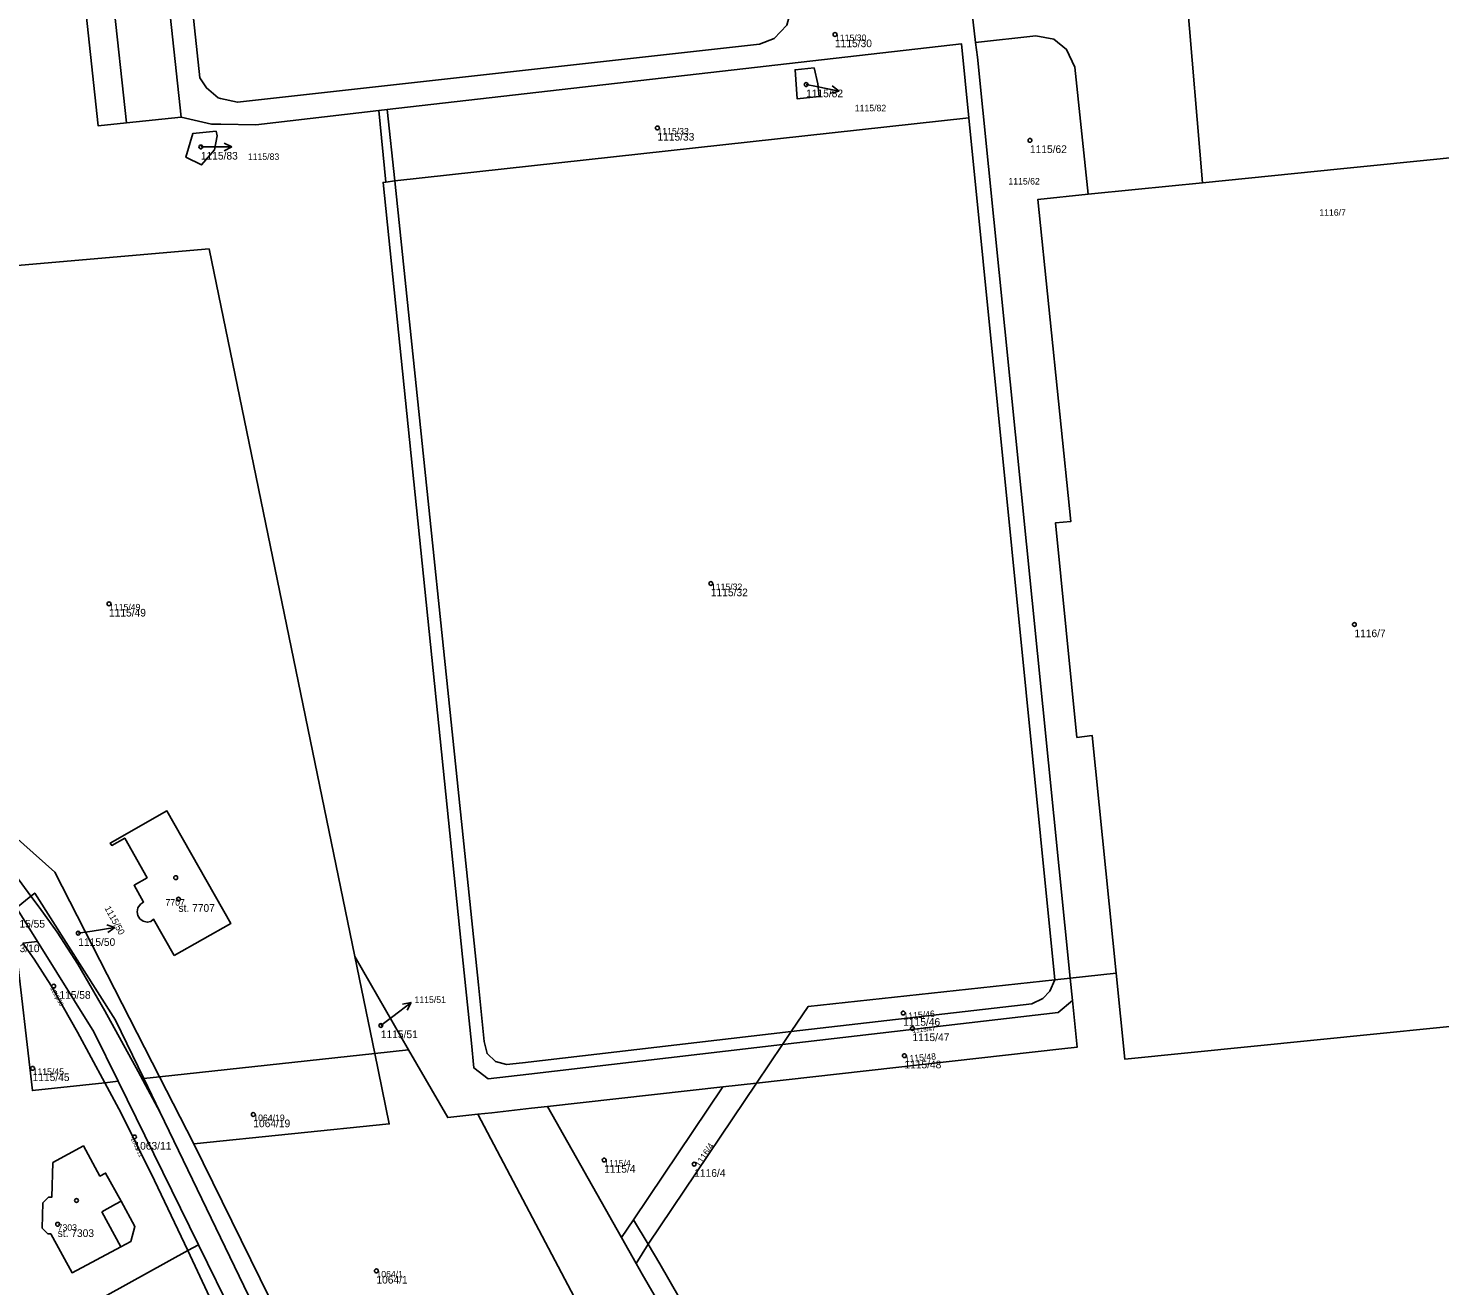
# Model space of a CAD drawing. Extents: x -543948 to -537130, y -1157612 to -1152122.
# Drawn here: x -539604.9 to -539420.2, y -1156400.3 to -1156235.7 of the extents above; entities that cross this region are included whole.
import ezdxf

# ---------------------------------------------------------------- set-up
doc = ezdxf.new("R2010")
doc.units = 0
for name, color, linetype in [('Definiční body', 7, 'Continuous'), ('Hranice parcel', 7, 'Continuous'), ('Parcelní čísla', 7, 'Continuous'), ('Pop  PČ popisy', 7, 'Continuous'), ('Vnitřní kresba', 7, 'Continuous')]:
    doc.layers.add(name, color=color, linetype=linetype)

msp = doc.modelspace()

# ---------------------------------------------------------------- linework, layer by layer
at = {"layer": 'Definiční body'}
for centre in [(-539499.3, -1156236.52994), (-539503.08, -1156243.07994), (-539522.54, -1156248.75994), (-539582.28, -1156251.23994), (-539473.79, -1156250.37994), (-539515.54, -1156308.37994), (-539594.3, -1156311.03994), (-539431.33, -1156313.73994), (-539585.57, -1156346.86994), (-539585.21, -1156349.67994), (-539598.32, -1156354.13994), (-539601.54, -1156361.05994), (-539490.37, -1156364.58994), (-539558.73, -1156366.20994), (-539489.17, -1156366.59994), (-539490.22, -1156370.16994), (-539604.3, -1156371.82994), (-539575.42, -1156377.86994), (-539590.97, -1156380.79994), (-539529.5, -1156383.81994), (-539517.72, -1156384.35994), (-539598.55, -1156389.10994), (-539601.02, -1156392.22994), (-539559.31, -1156398.32994)]:
    msp.add_circle(centre, 0.25, dxfattribs=at)
at = {"layer": 'Hranice parcel'}
for p, q in [((-539595.49, -1156215.97), (-539592.02, -1156248.1)), ((-539451.22, -1156255.93), (-539453.41, -1156229.63)), ((-539481.48, -1156232.65), (-539480.91, -1156237.57)), ((-539592.02, -1156248.1), (-539584.86, -1156247.33)), ((-539481.78, -1156247.42), (-539556.9, -1156255.68)), ((-539481.78, -1156247.42), (-539470.52, -1156360.23)), ((-539607.73, -1156344.92), (-539604.51, -1156349.29)), ((-539605.57, -1156355.43), (-539603.66, -1156355.21)), ((-539562.13, -1156357.18), (-539555.09, -1156369.4)), ((-539559.52, -1156369.88), (-539562.13, -1156357.18)), ((-539470.52, -1156360.23), (-539468.52, -1156360.01)), ((-539462.52, -1156359.36), (-539468.52, -1156360.01)), ((-539468.23, -1156362.94), (-539468.52, -1156360.01)), ((-539506.18, -1156368.72), (-539505.04, -1156367.02)), ((-539555.09, -1156369.4), (-539559.52, -1156369.88)), ((-539509.56, -1156373.75), (-539506.18, -1156368.72)), ((-539559.52, -1156369.88), (-539587.7, -1156372.94)), ((-539587.7, -1156372.94), (-539589.75, -1156373.16)), ((-539593.11, -1156373.52), (-539594.84, -1156373.71)), ((-539593.11, -1156373.52), (-539582.6, -1156394.91)), ((-539513.96, -1156374.24), (-539536.94, -1156376.82)), ((-539525.68, -1156391.66), (-539513.96, -1156374.24)), ((-539509.56, -1156373.75), (-539523.77, -1156394.85)), ((-539513.96, -1156374.24), (-539509.56, -1156373.75)), ((-539536.94, -1156376.82), (-539527.23, -1156393.96)), ((-539527.23, -1156393.96), (-539525.68, -1156391.66)), ((-539525.68, -1156391.66), (-539523.77, -1156394.85)), ((-539582.6, -1156394.91), (-539584, -1156395.68)), ((-539582.6, -1156394.91), (-539573.33, -1156413.75)), ((-539584, -1156395.68), (-539617.21, -1156414.01)), ((-539575.06, -1156414.65), (-539584, -1156395.68))]:
    msp.add_line(p, q, dxfattribs=at)
for points in [[(-539584.86, -1156247.33), (-539597.37, -1156131.17), (-539596.62, -1156128.94), (-539594.87, -1156127.75), (-539561.36, -1156124.05), (-539517.61, -1156119.21)], [(-539509.18, -1156237.78), (-539577.5, -1156245.39), (-539579.7, -1156244.89), (-539580, -1156244.82), (-539581.55, -1156243.51), (-539582.4, -1156242.19), (-539593.77, -1156135.82), (-539593.44, -1156133.31), (-539591.5, -1156131), (-539589.11, -1156130.23), (-539562.35, -1156127.29), (-539521.85, -1156122.83), (-539518.9, -1156124.09), (-539517.15, -1156126.01), (-539515.99, -1156128.84), (-539505.04, -1156233.24), (-539505.6, -1156235.31), (-539507.26, -1156237.06), (-539509.18, -1156237.78)], [(-539592.02, -1156248.1), (-539595.7, -1156248.5), (-539599.16, -1156216.36)], [(-539556.9, -1156255.68), (-539557.91, -1156246.35), (-539482.74, -1156237.75), (-539481.78, -1156247.42)], [(-539480.91, -1156237.57), (-539473.03, -1156236.7), (-539470.68, -1156237.13), (-539469, -1156238.47), (-539467.92, -1156240.79), (-539466.17, -1156257.44)], [(-539468.52, -1156360.01), (-539480.66, -1156239.51), (-539480.91, -1156237.57)], [(-539502.04, -1156240.91), (-539501.54, -1156243), (-539501.36, -1156244.62), (-539504.26, -1156244.93), (-539504.53, -1156241.14), (-539502.04, -1156240.91)], [(-539584.86, -1156247.33), (-539580.91, -1156248.24), (-539579.68, -1156248.26), (-539575.09, -1156248.34), (-539559, -1156246.48), (-539558.07, -1156255.83), (-539558.43, -1156255.88), (-539548.03, -1156357.24), (-539546.87, -1156368.51), (-539546.54, -1156371.77), (-539544.68, -1156373.19), (-539539.35, -1156372.57), (-539506.18, -1156368.72)], [(-539580.27, -1156249.17), (-539580.13, -1156249.78), (-539580.51, -1156251.61), (-539582.18, -1156253.6), (-539584.23, -1156252.6), (-539583.34, -1156249.5), (-539580.27, -1156249.17)], [(-539451.22, -1156255.93), (-539433.13, -1156254.11), (-539428.78, -1156253.67), (-539398.93, -1156250.66), (-539387.62, -1156363.22), (-539461.39, -1156370.62), (-539462.52, -1156359.36)], [(-539505.04, -1156367.02), (-539540.19, -1156371.09), (-539542.29, -1156371.33), (-539543.73, -1156370.93), (-539544.82, -1156369.88), (-539545.19, -1156368.33), (-539545.96, -1156360.89), (-539556.9, -1156255.68)], [(-539466.17, -1156257.44), (-539460.03, -1156256.82), (-539451.22, -1156255.93)], [(-539462.52, -1156359.36), (-539465.63, -1156328.27), (-539467.64, -1156328.52), (-539470.46, -1156300.44), (-539468.45, -1156300.26), (-539472.75, -1156258.1), (-539466.17, -1156257.44)], [(-539613.86, -1156267.42), (-539581.21, -1156264.59), (-539562.13, -1156357.18)], [(-539585.76, -1156357.05), (-539588.46, -1156352.32), (-539588.83, -1156352.61), (-539589.29, -1156352.7), (-539589.83, -1156352.55), (-539590.25, -1156352.25), (-539590.52, -1156351.81), (-539590.6, -1156351.33), (-539590.51, -1156350.81), (-539590.17, -1156350.34), (-539589.78, -1156350.07), (-539591.03, -1156347.85), (-539589.32, -1156346.88), (-539592.24, -1156341.69), (-539593.95, -1156342.65), (-539594.13, -1156342.34), (-539586.73, -1156338.14), (-539578.37, -1156352.87), (-539585.76, -1156357.05)], [(-539608.29, -1156339.98), (-539601.38, -1156346.14), (-539587.7, -1156372.94)], [(-539589.75, -1156373.16), (-539593.45, -1156365.5), (-539604.02, -1156348.89), (-539604.51, -1156349.29)], [(-539604.51, -1156349.29), (-539606.4, -1156350.81), (-539603.66, -1156355.21)], [(-539594.84, -1156373.71), (-539604.33, -1156374.74), (-539606.52, -1156355.54)], [(-539594.84, -1156373.71), (-539598.42, -1156367.07), (-539601.93, -1156360.95), (-539604.08, -1156357.55), (-539605.57, -1156355.43)], [(-539603.66, -1156355.21), (-539596.29, -1156367.06), (-539593.11, -1156373.52)], [(-539505.04, -1156367.02), (-539502.83, -1156363.73), (-539470.52, -1156360.23)], [(-539505.04, -1156367.02), (-539473.55, -1156363.37), (-539472.1, -1156362.68), (-539471.17, -1156361.7), (-539470.52, -1156360.23)], [(-539509.56, -1156373.75), (-539469.61, -1156369.27), (-539467.62, -1156369.05), (-539468.23, -1156362.94)], [(-539506.18, -1156368.72), (-539470.08, -1156364.52), (-539468.23, -1156362.94)], [(-539546.04, -1156377.83), (-539549.98, -1156378.27), (-539555.09, -1156369.4)], [(-539559.52, -1156369.88), (-539557.62, -1156379.09), (-539583.22, -1156381.7), (-539587.7, -1156372.94)], [(-539563.35, -1156427.84), (-539575.44, -1156402.8), (-539587.65, -1156377.51), (-539589.75, -1156373.16)], [(-539584, -1156395.68), (-539588.35, -1156386.52), (-539592.7, -1156377.68), (-539594.84, -1156373.71)], [(-539546.04, -1156377.83), (-539544.22, -1156377.63), (-539539.01, -1156377.05), (-539536.94, -1156376.82)], [(-539523.54, -1156417.22), (-539532.55, -1156403.4), (-539546.04, -1156377.83)], [(-539602.94, -1156389.43), (-539603.03, -1156392.72), (-539602.29, -1156393.49), (-539601.93, -1156393.5), (-539599.14, -1156398.57), (-539592.77, -1156395.17), (-539591.44, -1156394.47), (-539590.92, -1156392.52), (-539592.73, -1156389.21), (-539594.75, -1156385.52), (-539595.48, -1156385.93), (-539597.64, -1156381.98), (-539601.66, -1156384.16), (-539601.8, -1156388.69), (-539602.21, -1156388.68), (-539602.94, -1156389.43)], [(-539434.28, -1156563.31), (-539454.24, -1156517.51), (-539476.7, -1156481.18), (-539524.52, -1156398.74), (-539525.3, -1156397.36), (-539527.23, -1156393.96)], [(-539523.77, -1156394.85), (-539522.23, -1156397.42), (-539474.85, -1156479.9), (-539452.25, -1156516.35), (-539431.27, -1156560.89)]]:
    msp.add_lwpolyline(points, dxfattribs=at)
at = {"layer": 'Pop  PČ popisy'}
for p, q in [((-539503.08, -1156243.08), (-539501.72, -1156243.35)), ((-539501.72, -1156243.35), (-539498.774, -1156243.923)), ((-539498.774, -1156243.923), (-539499.853, -1156244.223)), ((-539498.774, -1156243.923), (-539499.662, -1156243.24)), ((-539581.23, -1156251.24), (-539582.28, -1156251.24)), ((-539581.23, -1156251.24), (-539578.229, -1156251.24)), ((-539578.229, -1156251.24), (-539579.23, -1156250.739)), ((-539578.229, -1156251.24), (-539579.23, -1156251.741)), ((-539598.32, -1156354.14), (-539596.5, -1156353.85)), ((-539596.5, -1156353.85), (-539593.536, -1156353.381)), ((-539593.536, -1156353.381), (-539594.603, -1156353.043)), ((-539593.536, -1156353.381), (-539594.447, -1156354.032)), ((-539557.18, -1156365.02), (-539554.783, -1156363.214)), ((-539554.783, -1156363.214), (-539555.884, -1156363.417)), ((-539554.783, -1156363.214), (-539555.282, -1156364.217)), ((-539558.73, -1156366.21), (-539557.18, -1156365.02))]:
    msp.add_line(p, q, dxfattribs=at)
at = {"layer": 'Vnitřní kresba'}
for p, q in [((-539559, -1156246.48), (-539557.91, -1156246.35)), ((-539558.07, -1156255.83), (-539556.9, -1156255.68)), ((-539604.51, -1156349.29), (-539603.44, -1156350.74)), ((-539603.44, -1156350.74), (-539601.09, -1156353.99)), ((-539601.09, -1156353.99), (-539598.37, -1156358.18)), ((-539598.37, -1156358.18), (-539594.84, -1156364.29)), ((-539594.84, -1156364.29), (-539590.5, -1156372.23)), ((-539590.5, -1156372.23), (-539587.65, -1156377.51)), ((-539560.82, -1156427.17), (-539583.22, -1156381.7)), ((-539595.25, -1156390.59), (-539593.47, -1156389.61)), ((-539593.47, -1156389.61), (-539592.73, -1156389.21)), ((-539592.77, -1156395.17), (-539595.25, -1156390.59)), ((-539523.77, -1156394.85), (-539525.3, -1156397.36))]:
    msp.add_line(p, q, dxfattribs=at)

# ---------------------------------------------------------------- texts
at = {"layer": 'Definiční body'}
for s, p in [('1115/30', (-539499.3, -1156238.186)), ('1115/82', (-539503.08, -1156244.736)), ('1115/33', (-539522.54, -1156250.416)), ('1115/62', (-539473.79, -1156252.036)), ('1115/83', (-539582.28, -1156252.896)), ('1115/32', (-539515.54, -1156310.036)), ('1115/49', (-539594.3, -1156312.696)), ('1116/7', (-539431.33, -1156315.396)), ('st. 7707', (-539585.21, -1156351.336)), ('1115/55', (-539607.51, -1156353.406)), ('1115/50', (-539598.32, -1156355.796)), ('1063/10', (-539608.23, -1156356.616)), ('1115/58', (-539601.54, -1156362.716)), ('1115/46', (-539490.37, -1156366.246)), ('1115/51', (-539558.73, -1156367.866)), ('1115/47', (-539489.17, -1156368.256)), ('1115/48', (-539490.22, -1156371.826)), ('1115/45', (-539604.3, -1156373.486)), ('1064/19', (-539575.42, -1156379.526)), ('1063/11', (-539590.97, -1156382.456)), ('1115/4', (-539529.5, -1156385.476)), ('1116/4', (-539517.72, -1156386.016)), ('st. 7303', (-539601.02, -1156393.886)), ('1064/1', (-539559.31, -1156399.986))]:
    msp.add_text(s, height=0.999996, dxfattribs=at).set_placement(p)
at = {"layer": 'Parcelní čísla'}
for s, p in [('1115/30', (-539499.3, -1156237.38)), ('1115/82', (-539496.70852, -1156246.58)), ('1115/33', (-539522.54, -1156249.61)), ('1115/83', (-539576.13183, -1156252.94)), ('1115/62', (-539476.60892, -1156256.15937)), ('1116/7', (-539435.92309, -1156260.24421)), ('1115/32', (-539515.54, -1156309.23)), ('1115/49', (-539594.3, -1156311.89)), ('7707', (-539586.90916, -1156350.53)), ('1115/51', (-539554.32, -1156363.26)), ('1115/45', (-539604.3, -1156372.68)), ('1064/19', (-539575.42, -1156378.72)), ('1115/4', (-539529.5, -1156384.67)), ('7303', (-539601.02, -1156393.08)), ('1064/1', (-539559.31, -1156399.18))]:
    msp.add_text(s, height=0.849999, dxfattribs=at).set_placement(p)
for s, height, rotation, p in [('1115/50', 0.849999, 298.9999972, (-539594.91757, -1156350.85891)), ('1115/58', 0.549999, 298.9999972, (-539602.021, -1156361.326)), ('1115/46', 0.849999, 5, (-539490.295, -1156365.436)), ('1115/47', 0.6, 6, (-539489.107, -1156367.196)), ('1115/48', 0.849999, 5, (-539490.145, -1156371.016)), ('1063/11', 0.549999, 295, (-539591.468, -1156381.032)), ('1116/4', 0.849999, 56, (-539517.015, -1156384.835))]:
    msp.add_text(s, height=height, rotation=rotation, dxfattribs=at).set_placement(p)

doc.saveas('drawing.dxf')
